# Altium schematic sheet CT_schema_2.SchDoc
size 383 x 311 mm
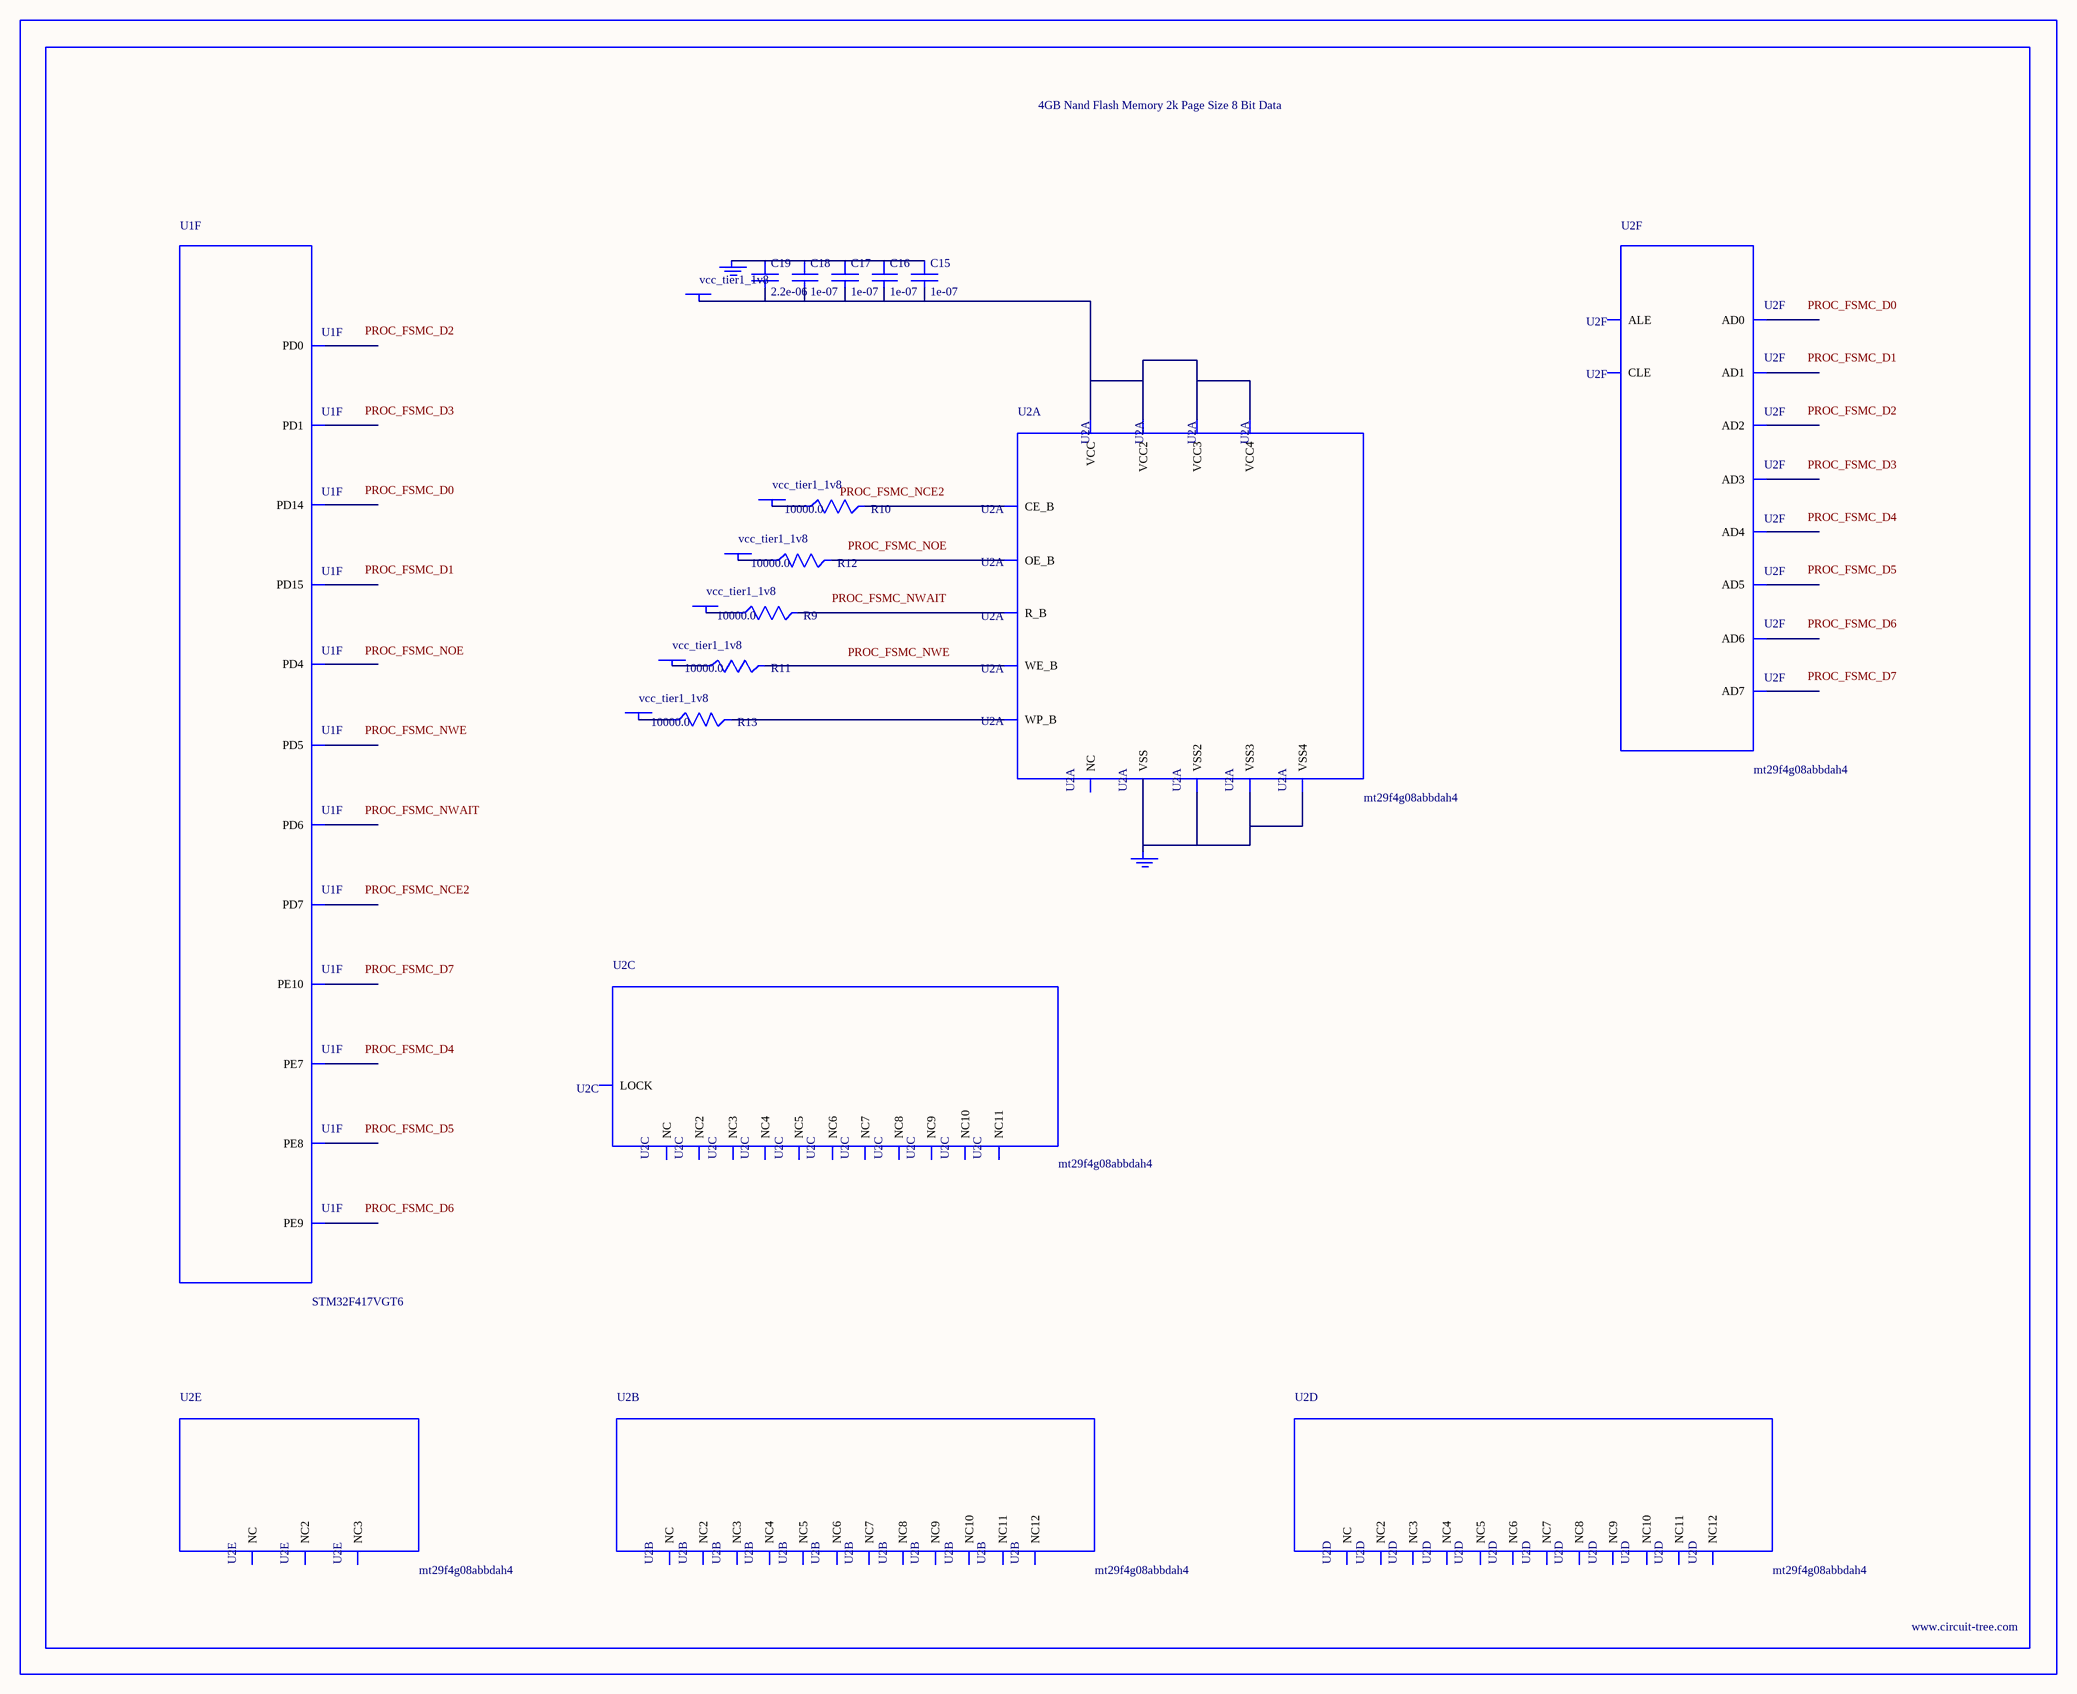
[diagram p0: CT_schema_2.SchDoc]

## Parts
BORDER1  (no value)
C15  1e-07  [C0402]
C16  1e-07  [C0402]
C17  1e-07  [C0402]
C18  1e-07  [C0402]
C19  2.2e-06  [C0603]
GND_INSTANCE_1_0  (no value)
GND_INSTANCE_1_1  (no value)
POWER_INSTANCE_1_0  vcc_tier1_1v8
POWER_INSTANCE_1_1  vcc_tier1_1v8
POWER_INSTANCE_1_2  vcc_tier1_1v8
POWER_INSTANCE_1_3  vcc_tier1_1v8
POWER_INSTANCE_1_4  vcc_tier1_1v8
POWER_INSTANCE_1_5  vcc_tier1_1v8
R9  10000.0  [R0603]
R10  10000.0  [R0603]
R11  10000.0  [R0603]
R12  10000.0  [R0603]
R13  10000.0  [R0603]
U1  STM32F417VGT6  [LQFP100]  (part F of 8)
U2  mt29f4g08abbdah4  [VFBGA-63]  (parts A,B,C,D,E,F of 6)

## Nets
NetC15_1: C15.1 C16.1 C17.1 C18.1 C19.1 GND_INSTANCE_1_0.0(GND)
NetC15_2: C15.2 C16.2 C17.2 C18.2 C19.2 POWER_INSTANCE_1_0.0(PWR) U2.D3(VCC) U2.G4(VCC2) U2.H8(VCC3) U2.J6(VCC4)
NetGND_INSTANCE_1_1_0: GND_INSTANCE_1_1.0(GND) U2.C5(VSS) U2.F7(VSS2) U2.K3(VSS3) U2.K8(VSS4)
NetPOWER_INSTANCE_1_1_0: POWER_INSTANCE_1_1.0(PWR) R9.1
NetPOWER_INSTANCE_1_2_0: POWER_INSTANCE_1_2.0(PWR) R10.1
NetPOWER_INSTANCE_1_3_0: POWER_INSTANCE_1_3.0(PWR) R11.1
NetPOWER_INSTANCE_1_4_0: POWER_INSTANCE_1_4.0(PWR) R12.1
NetPOWER_INSTANCE_1_5_0: POWER_INSTANCE_1_5.0(PWR) R13.1
NetR9_2: R9.2 U2.C8(R_B)
NetR10_2: R10.2 U2.C6(CE_B)
NetR11_2: R11.2 U2.C7(WE_B)
NetR12_2: R12.2 U2.D4(OE_B)
NetR13_2: R13.2 U2.C3(WP_B)

Not connected (* = marked no-connect by the designer): U1 38(PE7) 39(PE8) 40(PE9) 41(PE10) 61(PD14) 62(PD15) 81(PD0) 82(PD1) 85(PD4) 86(PD5) 87(PD6) 88(PD7); U2 A1(NC) A2(NC3) A9(NC4) A10(NC2) B1(NC5) B9(NC7) B10(NC6) C4(ALE) D5(CLE) D6(NC8) D7(NC9) D8(NC10) E3(NC11) E4(NC12) E5(NC) E6(NC2) E7(NC3) E8(NC4) F3(NC5) F4(NC6) F5(NC7) F6(NC8) F8(NC9) G3(NC) G5(LOCK) G6(NC10) G7(NC11) G8(NC) H3(NC2) H4(AD0) H5(NC3) H6(NC4) H7(NC5) J3(NC6) J4(AD1) J5(NC7) J7(AD5) J8(AD7) K4(AD2) K5(AD3) K6(AD4) K7(AD6) L1(NC8) L2(NC10) L9(NC11) L10(NC9) M1(NC12) M2(NC2) M9(NC3) M10(NC)

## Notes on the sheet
- Labels drawn without touching a wire or pin: PROC_FSMC_D0, PROC_FSMC_D1, PROC_FSMC_D2, PROC_FSMC_D3, PROC_FSMC_D4, PROC_FSMC_D5, PROC_FSMC_D6, PROC_FSMC_D7, PROC_FSMC_NCE2, PROC_FSMC_NOE, PROC_FSMC_NWAIT, PROC_FSMC_NWE

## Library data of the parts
BORDER1 = BORDER_PAGE1
C15-C18 = C0402C104K3RACTU
C19 = C0603C225K8RACTU
GND_INSTANCE_1_0 GND_INSTANCE_1_1 = GND
POWER_INSTANCE_1_0-POWER_INSTANCE_1_5 = PWR
R9-R13 = RC0603JR-0710KL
